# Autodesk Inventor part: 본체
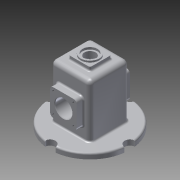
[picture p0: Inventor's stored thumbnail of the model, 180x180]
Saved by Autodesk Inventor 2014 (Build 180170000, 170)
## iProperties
Created: 2018-07
Part Number: 본체
Material: Aluminum 6061
Document SubType Name: Modeling
Designer: kh
Density: 2.71 g/cm^3
Appearance: Aluminum - Flat
Mass: 912.542 g
Surface Area: 1018.09 cm^2
Volume: 336.731 cm^3
Author: kh
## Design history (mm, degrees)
sketch "Sketch1"
  geometry: L1 (0, 0)-(0, 75); L2 (0, 0)-(75, 0); A1 r 75 centre (0, 0) between (0, 75) and (75, 0); 1 further point
  constraints: 4 end point, 2 point on circle, 1 centre point, 1 coincident, 1 perpendicular, 1 vertical
  dimensions: "d0" = 150 diameter of A1
extrude "Extrusion1" new body sketch "Sketch1" distance "d1" = 10; taper "d2" = 0 deg
sketch "Sketch2"
  geometry: L1 (0, 0)-(0, 75); L2 (0, 0)-(75, 0); A1 r 75 centre (0, 0) between (0, 75) and (75, 0) reference; 5 further points
  constraints: 4 end point, 2 point on circle, 1 coincident, 1 perpendicular, 1 vertical, 5 other
  dimensions: "d5" = 360 deg dimension on L1.start point (0, 75) (derived)
hole "Hole1" sketch "Sketch2" at (0, 75), (-75, 0), (0, -75), (75, 0) diameter "d7" = 20; stored, may be unused: countersink angle "d11" = 90 deg, drill point angle "d13" = 118 deg; dims "d8" = 6, "d9" = 4, "d10" = 2, "d12" = 8
sketch "Sketch3"
  geometry: L1 (65, 10)-(65, 0) reference; L2 (65, 0)-(-65, 0) reference; L3 (-65, 0)-(-65, 10) reference; L4 (-65, 10)-(65, 10) reference; L5 (0, 0)-(0, 10); L6 (-37, 0)-(37, 0); L7 (37, 0)-(37, 110); L8 (37, 110)-(-37, 110); L9 (-37, 110)-(-37, 0); L10 (-32, 0)-(32, 0); L11 (32, 0)-(32, 105); L12 (32, 105)-(-32, 105); L13 (-32, 105)-(-32, 0); 1 further point
  constraints: 18 end point, 4 midpoint, 4 parallel, 2 horizontal, 2 perpendicular, 2 other
  dimensions: "d14" = 110 distance between parallel lines of L8 L2; "d15" = 74 distance of L7.end L8.end; "d18" = 5 distance between parallel lines of L8 L12; "d19" = 5 distance between parallel lines of L9 L13
  node "Project Cut Edges1"
extrude "Extrusion2" join sketch "Sketch3" stored distance "d16" = 74; taper "d17" = 0 deg
extrude "Extrusion3" cut sketch "Sketch3" stored distance "d20" = 64; taper "d21" = 0 deg
sketch "Sketch4"
  geometry: L1 (65, 10)-(65, 0) reference; L2 (65, 0)-(32, 0) reference; L3 (32, 0)-(32, 105) reference; L4 (32, 105)-(-32, 105) reference; L5 (-32, 105)-(-32, 0) reference; L6 (-32, 0)-(-65, 0) reference; L7 (-65, 0)-(-65, 10) reference; L8 (-65, 10)-(-37, 10) reference; L9 (-37, 10)-(-37, 110) reference; L10 (-37, 110)-(37, 110) reference; L11 (37, 110)-(37, 10) reference; L12 (37, 10)-(65, 10) reference; L13 (-32, 80)-(-25, 77.452); L14 (-25, 77.452)-(-25, 55); L15 (-25, 55)-(-32, 55); L16 (-32, 55)-(-32, 80); 1 further point
  constraints: 8 end point, 2 perpendicular, 2 point on line, 1 collinear
  dimensions: "d22" = 55 distance from line of L14.end L6; "d23" = 50 diameter of L13.start L15; "d24" = 7 distance between parallel lines of L5 L14; "d25" = 110 deg angle of L5 L13
revolve "Revolution1" sketch "Sketch4" stored, may be unused: angle "d26" = 90 deg
mirror "Mirror1"
sketch "Sketch5"
  geometry: L1 (12, 20)-(62, 20); L2 (62, 20)-(62, 70); L3 (62, 70)-(12, 70); L4 (12, 70)-(12, 20); L5 (12, 20)-(62, 70); L6 (62, 20)-(12, 70); C1 r 25 at (37, 45) reference; 1 further point
  constraints: 12 end point, 2 midpoint, 2 parallel, 1 horizontal, 1 perpendicular
  dimensions: "d27" = 50 distance of L2.end L3.end; "d28" = 50 distance of L3.end L1.start
extrude "Extrusion4" join sketch "Sketch5" distance "d29" = 13; taper "d30" = 0 deg
mirror "Mirror2"
sketch "Sketch6"
  geometry: C1 r 22.452 at (37, 45) reference; C2 r 16 at (37, 45); 1 further point
  constraints: 1 centre point, 1 coincident
  dimensions: "d31" = 32 diameter of C2
extrude "Extrusion5" cut sketch "Sketch6" stored distance "d32" = 13; taper "d33" = 0 deg
sketch "Sketch7"
  geometry: L1 (0, 0)-(74, 0) reference; L2 (74, 74)-(74, 0) reference; L3 (0, 74)-(74, 74) reference; L4 (0, 0)-(0, 74) reference; L5 (17, 17)-(57, 17); L6 (57, 17)-(57, 57); L7 (57, 57)-(17, 57); L8 (17, 57)-(17, 17); L9 (17, 17)-(57, 57); L10 (57, 17)-(17, 57); 1 further point
  constraints: 12 end point, 2 midpoint, 2 parallel, 1 horizontal, 1 perpendicular
  dimensions: "d34" = 40 distance of L6.end L7.end; "d35" = 40 distance of L5.end L6.end
extrude "Extrusion6" join sketch "Sketch7" distance "d36" = 7; taper "d37" = 0 deg
sketch "Sketch8"
  geometry: C1 r 17.5 at (37, 37); 1 further point
  constraints: 1 centre point, 1 coincident
  dimensions: "d38" = 35 diameter of C1
extrude "Extrusion7" join sketch "Sketch8" distance "d39" = 3; taper "d40" = 0 deg
hole "Hole2" diameter "d43" = 21; stored, may be unused: countersink angle "d47" = 90 deg, drill point angle "d49" = 118 deg; dims "d41" = 10, "d42" = 10, "d44" = 6, "d45" = 28, "d46" = 4, "d48" = 8
fillet "Fillet1" dims "d50" = 6
fillet "Fillet2" dims "d51" = 6
sketch "Sketch9"
  geometry: L1 (64.567, -85.815)-(9.433, -85.815); L2 (9.433, -85.815)-(9.433, -74.185); L3 (9.433, -74.185)-(64.567, -74.185); L4 (64.567, -74.185)-(64.567, -85.815); L5 (64.567, -80)-(9.433, -80); L6 (37, -74.185)-(37, -85.815); L7 (19.5, -110)-(54.5, -110) reference; L8 (0, -100)-(0, 0) reference; 2 further points
  constraints: 5 midpoint, 4 end point, 2 other
  dimensions: "d52" = 30 distance from line of L7 point (37, -80); "d53" = 37 distance from line of L8 point (37, -80)
emboss "Emboss1" sketch "Sketch9" dims "d0" = 150, "d54" = 0.5, "d55" = 0
hole "Hole3" diameter "d58" = 3.459; stored, may be unused: countersink angle "d62" = 90 deg, drill point angle "d64" = 118 deg; dims "d56" = 10, "d57" = 10, "d59" = 8, "d60" = 28, "d61" = 4, "d63" = 10
pattern_circular "Circular Pattern1" dims angle "d66" = 360 deg
mirror "Mirror3"
fillet "Fillet3" dims "d68" = 8
fillet "Fillet4" dims "d69" = 8
fillet "Fillet5" dims "d70" = 3
fillet "Fillet6" dims "d71" = 3
fillet "Fillet7" dims "d72" = 3
chamfer "Chamfer1" distance "d73" = 1; stored, may be unused: second distance "d74" = 2, angle "d75" = 45 deg
fillet "Fillet8" dims "d76" = 3
fillet "Fillet9" dims "d77" = 3
fillet "Fillet10" dims "d78" = 3
body "Solid1"
node "Projected Loop1"
node "Projected Loop2"
node "Project Cut Edges2"
